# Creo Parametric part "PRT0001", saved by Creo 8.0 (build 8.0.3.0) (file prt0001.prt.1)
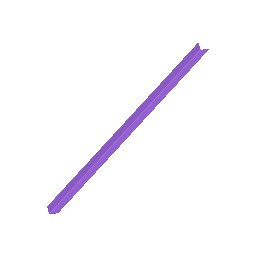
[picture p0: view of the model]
Units: millimeter Newton Second (mmNs); MM, TONNE, SECS

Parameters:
  SMT_DFLT_BEND_REL_LENGTH_TYPE = "Through All"

Other parameters: SMT_THICKNESS, SMT_PART_BEND_ALLOWANCE_FACTOR, SMT_DFLT_BEND_RADIUS, SMT_DFLT_BEND_ANGLE, SMT_DFLT_CRNR_REL_WIDTH, SMT_DFLT_CRNR_REL_DEPTH, SMT_DFLT_BEND_REL_WIDTH, SMT_DFLT_BEND_REL_DEPTH, SMT_DFLT_BEND_REL_LENGTH, SMT_DFLT_BEND_REL_ANGLE, SMT_GAP, SMT_DFLT_EDGE_TREA_WIDTH, SMT_DFLT_MITER_CUT_WIDTH, SMT_DFLT_MITER_CUT_OFFSET

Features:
  1. datum plane "DTM1"
  2. datum plane "DTM2"

Surfaces: 12 plane, 2 cylinder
